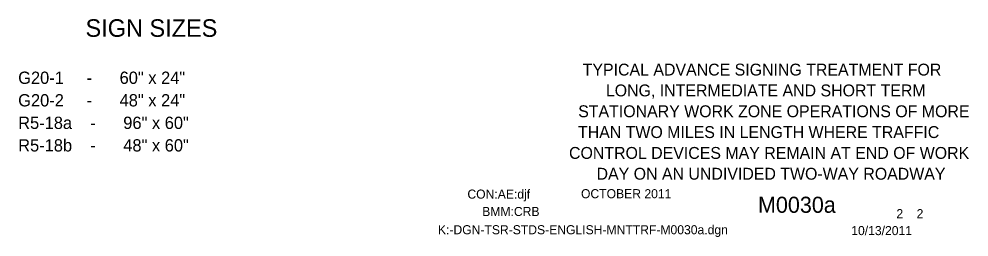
# Model space of a CAD drawing. Extents: x 16734 to 18468, y 5860 to 6911.
# Drawn here: x 17803 to 18452, y 5860 to 6009 of the extents above; entities that cross this region are included whole.
import ezdxf

# ---------------------------------------------------------------- set-up
doc = ezdxf.new("R2010")
doc.units = 0
for name, color, linetype in [('BORDER_SIGNAL_WO', 7, 'Continuous'), ('TYPICAL_EX', 7, 'Continuous'), ('TYPICAL_TEXT_DIMEN_PR', 7, 'Continuous')]:
    doc.layers.add(name, color=color, linetype=linetype)

msp = doc.modelspace()

# ---------------------------------------------------------------- texts
at = {"layer": 'BORDER_SIGNAL_WO'}
for s, height, p in [('CON:AE:djf', 6.2, (18108.93, 5885.858)), ('    OCTOBER 2011    ', 6.2, (18177.324, 5886.139)), ('    M0030a   ', 11, (18291.105, 5876.18)), ('BMM:CRB   ', 6.2, (18119.053, 5873.974)), (' 2    2 ', 6.2, (18399.689, 5872.498)), ('K:-DGN-TSR-STDS-ENGLISH-MNTTRF-M0030a.dgn        ', 6.2, (18088.797, 5861.511)), ('10/13/2011    ', 6.19999, (18371.171, 5860.93))]:
    msp.add_text(s, height=height, dxfattribs=at).set_placement(p)
at = {"layer": 'TYPICAL_EX'}
for s, p in [('TYPICAL ADVANCE SIGNING TREATMENT FOR ', (18187.687, 5969.987)), ('LONG, INTERMEDIATE AND SHORT TERM', (18203.529, 5955.751)), ('STATIONARY WORK ZONE OPERATIONS OF MORE', (18184.621, 5941.514)), ('THAN TWO MILES IN LENGTH WHERE TRAFFIC ', (18184.486, 5927.278)), ('CONTROL DEVICES MAY REMAIN AT END OF WORK', (18178.354, 5913.042)), (' DAY ON AN UNDIVIDED TWO-WAY ROADWAY', (18194.153, 5898.806))]:
    msp.add_text(s, height=8.12248, dxfattribs=at).set_placement(p)
at = {"layer": 'TYPICAL_TEXT_DIMEN_PR'}
for s, height, p in [('SIGN SIZES', 12, (17848.04, 5996.454)), ('G20-1     -      60" x 24"', 8.4, (17802.02, 5964.282)), ('G20-2     -      48" x 24"', 8.4, (17802.02, 5948.882)), ('R5-18a    -      96" x 60"', 8.4, (17802.02, 5933.482)), ('R5-18b    -      48" x 60"', 8.4, (17802.02, 5918.082))]:
    msp.add_text(s, height=height, dxfattribs=at).set_placement(p)

doc.saveas('drawing.dxf')
